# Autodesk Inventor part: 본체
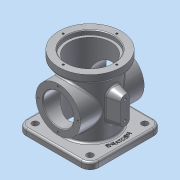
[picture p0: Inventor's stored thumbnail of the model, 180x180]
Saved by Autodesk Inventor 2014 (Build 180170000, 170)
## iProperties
Created: 2021-03
Part Number: 본체
Material: 알루미늄 6061
Document SubType Name: Modeling
Designer: net
Density: 2.71 g/cm^3
Appearance: 알루미늄 - 평지
Mass: 833.807 g
Surface Area: 863.847 cm^2
Volume: 307.678 cm^3
Author: net
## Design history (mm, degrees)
sketch "스케치1"
  geometry: L1 (-57, 57)-(57, 57); L2 (57, 57)-(57, -57); L3 (57, -57)-(-57, -57); L4 (-57, -57)-(-57, 57); 3 further points
  constraints: 8 end point, 2 midpoint, 2 parallel, 2 perpendicular, 1 horizontal, 1 horizontal alignment, 1 vertical alignment
  dimensions: "d0" = 114 distance of L3.end L1.start
extrude "돌출1" new body sketch "스케치1" distance "d1" = 10; taper "d2" = 0 deg
sketch "스케치2"
  geometry: L1 (57, 10)-(-57, 10) reference; L2 (49, 111)-(49, 98); L3 (49, 98)-(38, 98); L4 (38, 98)-(38, 10); L5 (33, 10)-(33, 104); L6 (33, 104)-(37, 104); L7 (37, 104)-(37, 111); L8 (0, 111)-(0, 10); L9 (49, 111)-(0, 111); L10 (-57, 0)-(57, 0) reference; L11 (38, 10)-(0, 10); 1 further point
  constraints: 18 end point, 3 point on line, 2 perpendicular, 1 collinear, 1 midpoint, 1 vertical alignment
  dimensions: "d4" = 7 distance between parallel lines of L6 L9; "d5" = 13 distance between parallel lines of L9 L3; "d6" = 98 diameter of L2 L8; "d7" = 74 diameter of L7 L8; "d8" = 66 diameter of L5 L8; "d9" = 76 diameter of L4 L8; "d11" = 104 distance between parallel lines of L10 L6
revolve "회전1" sketch "스케치2" stored, may be unused: angle "d10" = 90 deg
sketch "스케치3"
  geometry: L1 (-61.35, 54)-(61.35, 54); L2 (-57, 0)-(57, 0) reference; L3 (-50, 54)-(-50, 78); L4 (-50, 78)-(50, 78); L5 (50, 78)-(50, 54); L6 (50, 78)-(50, 89); L7 (50, 89)-(-50, 89); L8 (-50, 89)-(-50, 78); 4 further points
  constraints: 14 end point, 3 midpoint, 3 perpendicular, 2 parallel, 2 point on line, 2 vertical alignment, 1 collinear, 1 horizontal
  dimensions: "d12" = 54 distance between parallel lines of L2 L1; "d13" = 48 diameter of L4 L1; "d14" = 70 diameter of L7 L1; "d15" = 50 distance from line of L3 point (0, 54)
revolve "회전2" stored, may be unused: angle "d16" = 90 deg
revolve "회전3" stored, may be unused: angle "d17" = 90 deg
node "작업 평면1"
sketch "스케치4"
  geometry: L1 (0, 70)-(0, 41); L2 (-7, 70)-(-7, 41); L3 (7, 41)-(7, 70); L4 (0, 77)-(18.274, 77); L5 (0, 34)-(18.274, 34); L6 (0, 55.5)-(16.933, 55.5); L7 (-50, 30)-(-50, 78) reference; L8 (57, 0)-(-57, 0) reference; A1 r 7 centre (0, 70) between (7, 70) and (-7, 70); A2 r 7 centre (0, 41) between (-7, 41) and (7, 41); 3 further points
  constraints: 14 end point, 6 point on circle, 6 tangent, 3 midpoint, 3 parallel, 2 centre point, 1 perpendicular, 1 vertical, 1 vertical alignment
  dimensions: "d19" = 43 distance between parallel lines of L5 L4; "d20" = 20 vertical distance of L5.start point (-50, 54); "d21" = 14 distance between parallel lines of L3 L2
extrude "돌출2" join sketch "스케치4" stored distance "d22" = 10; taper "d23" = 15 deg
sketch "스케치5"
  geometry: C1 r 24 at (0, 0) reference; 2 further points
  constraints: 1 vertical alignment
hole "구멍1" sketch "스케치5" at (0, 31) diameter "d25" = 3.242; stored, may be unused: countersink angle "d29" = 90 deg, drill point angle "d31" = 118 deg; dims "d26" = 6, "d27" = 4, "d28" = 2, "d30" = 8
sketch "스케치6"
  geometry: C1 r 33 at (0, 0) reference
extrude "돌출3" cut sketch "스케치6" stored distance "d35" = 10; taper "d36" = 0 deg
fillet "모깎기1" dims "d37" = 14
sketch "스케치7"
  geometry: 1 further point
hole "구멍2" sketch "스케치7" at (0, 42) diameter "d39" = 3.242; stored, may be unused: countersink angle "d43" = 90 deg, drill point angle "d45" = 118 deg; dims "d40" = 6, "d41" = 4, "d42" = 2, "d44" = 8
sketch "스케치8"
  geometry: A1 r 7 centre (-41, 0) between (-41, -7) and (-41, 7) reference; A2 r 7 centre (-70, 0) between (-70, 7) and (-70, -7) reference; 1 further point
hole "구멍3" sketch "스케치8" at (-70, 0), (-41, 0) diameter "d49" = 4.134; stored, may be unused: countersink angle "d53" = 90 deg, drill point angle "d55" = 118 deg; dims "d50" = 8, "d51" = 4, "d52" = 2, "d54" = 10
sketch "스케치9"
  geometry: A1 r 14 centre (-43, 43) between (-43, 57) and (-57, 43) reference; A2 r 14 centre (-43, -43) between (-57, -43) and (-43, -57) reference; A3 r 14 centre (43, -43) between (43, -57) and (57, -43) reference; A4 r 14 centre (43, 43) between (57, 43) and (43, 57) reference
hole "구멍4" sketch "스케치9" at (43, -43), (-43, -43), (43, 43), (-43, 43) diameter "d56" = 10; stored, may be unused: countersink angle "d60" = 90 deg, drill point angle "d62" = 118 deg; dims "d57" = 8, "d58" = 4, "d59" = 2, "d61" = 10
chamfer "모따기1" distance "d63" = 1; stored, may be unused: second distance "d64" = 2, angle "d65" = 45 deg
fillet "모깎기2" dims "d66" = 3
sketch "스케치10"
  geometry: C1 r 41 at (0, 0) reference; C2 r 50 at (0, 0)
  constraints: 1 centre point, 1 coincident, 1 other
  dimensions: "d67" = 100 diameter of C2
feature "엠보싱1" sketch "스케치10" dims "d0" = 114, "d68" = 0.5, "d69" = 0
fillet "모깎기3" dims "d70" = 3
node "솔리드1"
pattern_circular "원형 패턴1" dims angle "d33" = 360 deg
mirror "대칭1"
pattern_circular "원형 패턴2" dims angle "d47" = 360 deg
other parameters: "d18" = 55
